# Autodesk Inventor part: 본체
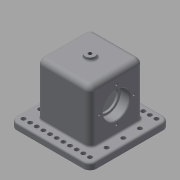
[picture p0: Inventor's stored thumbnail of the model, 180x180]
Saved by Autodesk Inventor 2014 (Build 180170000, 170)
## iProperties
Created: 2018-11
Part Number: 본체
Material: Generic
Document SubType Name: Modeling
Designer: kh
Density: 1 g/cm^3
Appearance: Default
Author: kh
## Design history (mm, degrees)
sketch "스케치1"
  geometry: L1 (-60, 60)-(60, 60); L2 (60, 60)-(60, -60); L3 (60, -60)-(-60, -60); L4 (-60, -60)-(-60, 60); L5 (-60, 60)-(60, -60); L6 (60, 60)-(-60, -60); L7 (-23, 23)-(23, 23); L8 (23, 23)-(23, -23); L9 (23, -23)-(-23, -23); L10 (-23, -23)-(-23, 23); L11 (-23, 23)-(23, -23); L12 (23, 23)-(-23, -23); 1 further point
  constraints: 24 end point, 4 midpoint, 4 parallel, 2 horizontal, 2 perpendicular, 1 point on line
  dimensions: "d0" = 120 distance of L2.end L3.end; "d1" = 120 distance of L1.end L2.end; "d8" = 46 distance of L8.end L9.end
extrude "돌출1" new body sketch "스케치1" distance "d2" = 10; taper "d3" = 0 deg
sketch "스케치2"
  geometry: L1 (-40, 40)-(40, 40); L2 (40, 40)-(40, -40); L3 (40, -40)-(-40, -40); L4 (-40, -40)-(-40, 40); L5 (-40, 40)-(40, -40); L6 (40, 40)-(-40, -40); 1 further point
  constraints: 12 end point, 2 midpoint, 2 parallel, 1 horizontal, 1 perpendicular
  dimensions: "d4" = 80 distance of L2.end L3.end; "d5" = 80 distance of L1.end L2.end
extrude "돌출2" join sketch "스케치2" distance "d6" = 80; taper "d7" = 0 deg
extrude "돌출3" cut sketch "스케치1" distance "d9" = 80; taper "d10" = 0 deg
sketch "스케치3"
  geometry: C1 r 7.5 at (0, 0); 1 further point
  constraints: 1 centre point, 1 coincident
  dimensions: "d11" = 15 diameter of C1
extrude "돌출4" join sketch "스케치3" distance "d12" = 5; taper "d13" = 0 deg
sketch "스케치5"
  geometry: L1 (-40, 10)-(-40, 90) reference; L2 (40, 10)-(40, 90) reference; L3 (-60, 0)-(60, 0) reference; L4 (-40, 48)-(40, 48); L5 (-40, 48)-(-40, 68); L6 (-26, 68)-(-26, 64.5); L7 (-26, 64.5)-(26, 64.5); L8 (26, 64.5)-(26, 68); L9 (26, 68)-(40, 68); L10 (40, 68)-(40, 48); L11 (-40, 68)-(-26, 68); 1 further point
  constraints: 16 end point, 4 perpendicular, 4 point on line, 3 collinear, 2 parallel
  dimensions: "d16" = 48 distance between parallel lines of L4 L3; "d17" = 40 diameter of L11 L4; "d18" = 33 diameter of L7 L4; "d19" = 14 distance of L5.end L6.start
revolve "회전1" sketch "스케치5" stored, may be unused: angle "d20" = 90 deg
sketch "스케치6" dims "d21" = 52
  geometry: L1 (38, 40)-(64, 40); C1 r 20 at (38, 40) reference; 2 further points
  constraints: 2 coincident, 2 end point, 1 horizontal, 1 horizontal alignment, 2 other
hole "구멍1" sketch "스케치6" at (64, 40) diameter "d22" = 3.459; stored, may be unused: countersink angle "d26" = 90 deg, drill point angle "d28" = 118 deg; dims "d23" = 8, "d24" = 4, "d25" = 2, "d27" = 10
fillet "모깎기1" dims "d32" = 10
sketch "스케치7" dims "d38" = 10, "d45" = 10
  geometry: L1 (23, -23)-(23, 23) reference; L2 (23, 23)-(-23, 23) reference; L3 (-23, 23)-(-23, -23) reference; L4 (-23, -23)-(23, -23) reference; L5 (60, 50)-(60, -50) reference; L6 (50, -60)-(-50, -60) reference; L7 (-60, -50)-(-60, 50) reference; L8 (-50, 60)-(50, 60) reference; L9 (0, 60)-(0, -60); L10 (-60, 0)-(60, 0); A1 r 10 centre (50, 50) between (60, 50) and (50, 60) reference; A2 r 10 centre (50, -50) between (50, -60) and (60, -50) reference; A3 r 10 centre (-50, -50) between (-60, -50) and (-50, -60) reference; A4 r 10 centre (-50, 50) between (-50, 60) and (-60, 50) reference; 30 further points
  constraints: 14 symmetric about line, 4 end point, 4 midpoint, 1 coincident, 1 horizontal, 1 vertical, 14 other
  dimensions: "d35" = 10 distance of point (-50, 50) point (-40, 50); "d42" = 25 distance of point (-50, 50) point (-50, 25)
hole "구멍2" sketch "스케치7" diameter "d47" = 6.6; stored, may be unused: countersink angle "d51" = 90 deg, drill point angle "d53" = 118 deg; dims "d48" = 8, "d49" = 4, "d50" = 2, "d52" = 10
fillet "모깎기2" dims "d54" = 8
fillet "모깎기3" dims "d55" = 8, "d56" = 3
fillet "모깎기4" dims "d57" = 3, "d58" = 0.6
hole "구멍3" diameter "d61" = 5.242; stored, may be unused: countersink angle "d65" = 90 deg, drill point angle "d67" = 118 deg; dims "d59" = 10, "d60" = 10, "d62" = 8, "d63" = 4, "d64" = 2, "d66" = 10
chamfer "모따기1" distance "d68" = 1; stored, may be unused: second distance "d69" = 2, angle "d70" = 45 deg
node "솔리드1"
pattern_circular "원형 패턴1" dims angle "d30" = 360 deg
mirror "대칭1"
node "투영된 루프1"
